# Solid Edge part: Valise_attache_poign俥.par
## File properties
Author: Bernard DUMAS
Template: Normal.par
Last saved by: FR026244
Revision: 22
Application: Solid Edge
Material: Bois, Frêne
Style de face: Jaune kaki
Style de remplissage: Liège
Style virtuel: Frêne verni
Coef. of Thermal Exp: 0.0
Thermal Conductivity: 0.0
Specific Heat: 0.0
Modulus of Elasticity: 0.0
Poission's Ratio: 0.0
Yield Stress: 0.0
Ultimate Stress: 0.0
Elongation: 0.0
Densité: 460.000 kg/m^3
Précision: 0.9900
Document Number: 12
Revision: a
Project Name: Slamson
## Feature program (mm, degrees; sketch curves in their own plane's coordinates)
sketch for "unnamed Protrusion 1" plane through (0, 0, 0) normal (0, -1, 0) x-axis (1, 0, 0)
  line (0, 13.5) -> (-24, 13.5)
  arc centre (-24, -16.3981) radius 29.8981 from (-24, 13.5) to (-49, 0) ccw
  line (0, 0) -> (-49, 0)
  line (0, 13.5) -> (0, 0)
  dimension (linear) = 49
extrude "unnamed Protrusion 1" add finite 3 along +normal
mirror "unnamed Mirror 1" of "unnamed Protrusion 1" about plane through (0, 0, 0) normal (0, 0, 1)
extrude "unnamed Protrusion 2" add finite 3
mirror "unnamed Mirror 2" of "unnamed Protrusion 1", "unnamed Mirror 1" about plane through (0, 0, 0) normal (1, 0, 0)
extrude "unnamed Protrusion 3" add finite 3
extrude "unnamed Protrusion 4" add finite 3
sketch for "Perçage_1" plane through (0, -3, 0) normal (0, -1, 0) x-axis (1, 0, 0)
  hole centre (-30, 6.5) bore radius 1.5
hole "Perçage_1" diameter 3 through
sketch for "unnamed Hole 1" plane through (0, -3, 0) normal (0, -1, 0) x-axis (1, 0, 0)
  hole centre (-31, -6.5) bore radius 1.5
hole "unnamed Hole 1" through
sketch for "unnamed Hole 2" plane through (0, -3, 0) normal (0, -1, 0) x-axis (1, 0, 0)
  hole centre (41, 0) bore radius 1.5
hole "unnamed Hole 2" through
sketch for "unnamed Hole 3" plane through (0, -3, 0) normal (0, -1, 0) x-axis (1, 0, 0)
  hole centre (30, 6.5) bore radius 1.5
hole "unnamed Hole 3" through
sketch for "unnamed Hole 4" plane through (0, -3, 0) normal (0, -1, 0) x-axis (1, 0, 0)
  hole centre (31, -6.5) bore radius 1.5
hole "unnamed Hole 4" through
sketch for "unnamed Hole 5" plane through (0, -3, 0) normal (0, -1, 0) x-axis (1, 0, 0)
  hole centre (-41, 0) bore radius 1.5
hole "unnamed Hole 5" through
pattern "unnamed Pattern 1" of "Perçage_1", "unnamed Hole 1", "unnamed Hole 2", "unnamed Hole 3", "unnamed Hole 4", "unnamed Hole 5"
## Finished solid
Body 1: solid body, 14 faces, 30 edges, 12 vertices.
  Faces by surface: cylinder 10, plane 4
  Edges by curve: circle 20, line 10
Bounding box of the edges (mm): 98.000 x 3.000 x 27.000, from (-49, -3, -13.5) to (49, 0, 13.5).
Cylindrical faces by radius (mm): R1.5 x6, R29.8981 x4
Planar faces by outward normal: +y 1, +z 1, -y 1, -z 1
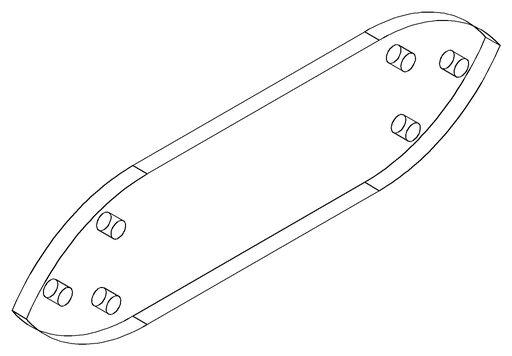
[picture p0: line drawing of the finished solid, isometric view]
